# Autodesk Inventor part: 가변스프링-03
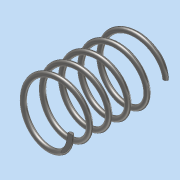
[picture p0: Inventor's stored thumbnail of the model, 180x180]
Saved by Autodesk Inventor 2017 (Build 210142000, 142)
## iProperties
Part Number: 가변스프링-03
Material: 강철, 연강
Document SubType Name: Modeling
Designer: MRC
Mass: 8.42563 g
Surface Area: 21.7273 cm^2
Volume: 1.07333 cm^3
Density: 7.85 g/cm^3
Appearance: 반연마
Author: MRC
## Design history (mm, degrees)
sketch "스케치1"
  geometry: L1 (0, 0)-(0, 37.411); L2 (0, 0)-(11, 0); L3 (0, 37.411)-(11, 37.411); C1 r 1 at (11, 0)
  constraints: 6 end point, 2 horizontal, 1 centre point, 1 coincident, 1 vertical
  dimensions: "d0" = 37.4112 distance of L1.start L1.end (derived); "d1" = 11 distance of L1.start L2.end; "d2" = 2 diameter of C1
feature "코일1" sketch "스케치1" pitch "d3" = 10; turns "d5" = 5; dims "d4" = 37.4112 (= d0), "d6" = 0, angle "d7" = 90 deg, angle "d8" = 90 deg, "d9" = 0, "d10" = 0
sketch "스케치2"
  geometry: L1 (37.411, 15)-(0, 15); L2 (0, 15)-(0, -15); L3 (0, -15)-(37.411, -15); L4 (37.411, -15)-(37.411, 15); 2 further points
  constraints: 8 end point, 2 parallel, 1 coincident, 1 horizontal, 1 midpoint, 1 perpendicular
  dimensions: "d11" = 37.4112 distance of L1.start L1.end (= d0); "d12" = 30 distance of L3.end L1.start
extrude "돌출1" sketch "스케치2" stored distance "d13" = 0; taper "d14" = 0 deg
node "솔리드1"
